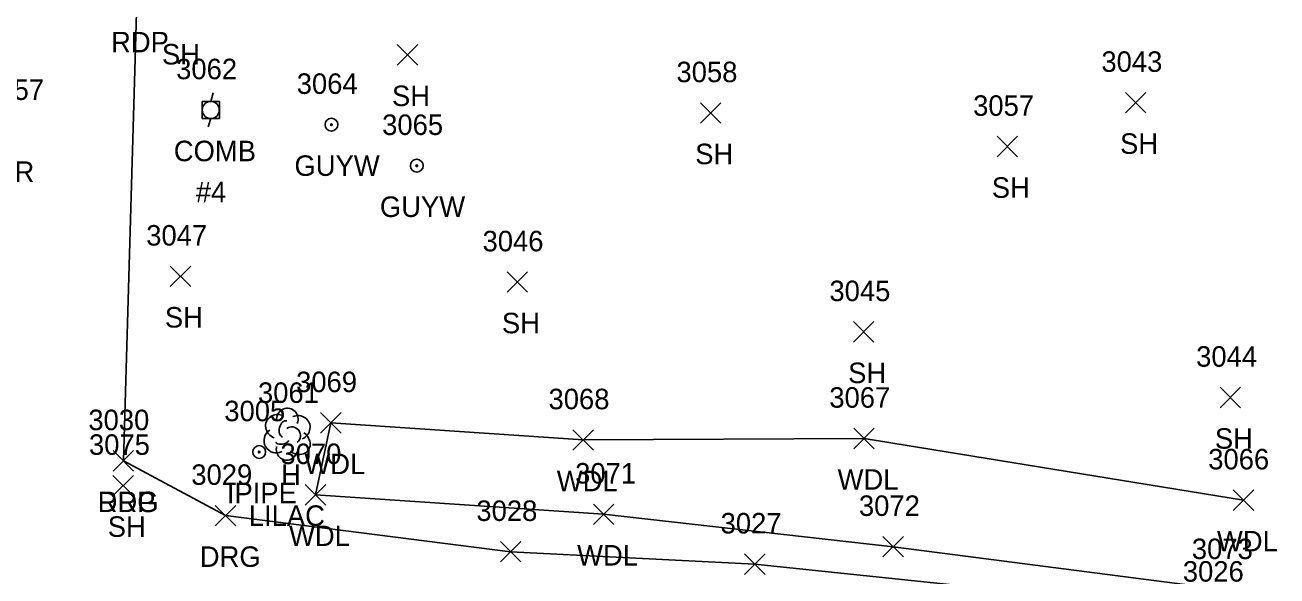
# Model space of a CAD drawing. Extents: x 1609623 to 1616187, y 756677 to 762826.
# Drawn here: x 1610613 to 1610735.2, y 762176.6 to 762230.4 of the extents above; entities that cross this region are included whole.
import ezdxf

# ---------------------------------------------------------------- set-up
doc = ezdxf.new("R2010")
doc.units = 0
for name, color, linetype in [('L_A', 7, 'Continuous'), ('L_C', 7, 'Continuous'), ('L_I', 7, 'Continuous'), ('L_TIC', 7, 'Continuous'), ('LAWA', 7, 'Continuous'), ('LTD', 7, 'Continuous'), ('M_A', 7, 'Continuous'), ('M_I', 7, 'Continuous'), ('MPIP', 7, 'Continuous'), ('P_A', 7, 'Continuous'), ('P_I', 7, 'Continuous'), ('P_TIC', 7, 'Continuous'), ('PET', 7, 'Continuous'), ('R_A', 7, 'Continuous'), ('R_I', 7, 'Continuous'), ('R_TIC', 7, 'Continuous'), ('RDG', 7, 'Continuous'), ('U_A', 7, 'Continuous'), ('U_C', 7, 'Continuous'), ('U_I', 7, 'Continuous'), ('UP', 7, 'Continuous'), ('UPGW', 7, 'Continuous')]:
    doc.layers.add(name, color=color, linetype=linetype)

msp = doc.modelspace()

# ---------------------------------------------------------------- linework, layer by layer
at = {"layer": 'L_TIC'}
for points in [[(1610649.3, 762226.48), (1610651.3, 762228.48)], [(1610651.3, 762226.48), (1610649.3, 762228.48)], [(1610720.38, 762221.82), (1610722.38, 762223.82)], [(1610722.38, 762221.82), (1610720.38, 762223.82)], [(1610678.9, 762220.81), (1610680.9, 762222.81)], [(1610680.9, 762220.81), (1610678.9, 762222.81)], [(1610707.85, 762217.53), (1610709.85, 762219.53)], [(1610709.85, 762217.53), (1610707.85, 762219.53)], [(1610627.14, 762204.87), (1610629.14, 762206.87)], [(1610629.14, 762204.87), (1610627.14, 762206.87)], [(1610660.03, 762204.31), (1610662.03, 762206.31)], [(1610662.03, 762204.31), (1610660.03, 762206.31)], [(1610693.83, 762199.45), (1610695.83, 762201.45)], [(1610695.83, 762199.45), (1610693.83, 762201.45)], [(1610729.63, 762193.05), (1610731.63, 762195.05)], [(1610731.63, 762193.05), (1610729.63, 762195.05)], [(1610641.82, 762190.57), (1610643.82, 762192.57)], [(1610643.82, 762190.57), (1610641.82, 762192.57)], [(1610666.46, 762188.9), (1610668.46, 762190.9)], [(1610668.46, 762188.9), (1610666.46, 762190.9)], [(1610693.87, 762189.05), (1610695.87, 762191.05)], [(1610695.87, 762189.05), (1610693.87, 762191.05)], [(1610621.55, 762184.45), (1610623.55, 762186.45)], [(1610623.55, 762184.45), (1610621.55, 762186.45)], [(1610640.33, 762183.55), (1610642.33, 762185.55)], [(1610642.33, 762183.55), (1610640.33, 762185.55)], [(1610730.91, 762183.03), (1610732.91, 762185.03)], [(1610732.91, 762183.03), (1610730.91, 762185.03)], [(1610668.45, 762181.65), (1610670.45, 762183.65)], [(1610670.45, 762181.65), (1610668.45, 762183.65)], [(1610696.71, 762178.49), (1610698.71, 762180.49)], [(1610698.71, 762178.49), (1610696.71, 762180.49)]]:
    msp.add_lwpolyline(points, dxfattribs=at)
at = {"layer": 'LAWA'}
msp.add_lwpolyline([(1610731.91, 762184.03), (1610694.87, 762190.05), (1610667.46, 762189.9), (1610642.82, 762191.57), (1610641.33, 762184.55), (1610669.45, 762182.65), (1610697.71, 762179.49), (1610730.21, 762175.28)], dxfattribs=at)
at = {"layer": 'LTD'}
msp.add_line((1610638.53, 762190.52), (1610638.53, 762190.52), dxfattribs=at)
msp.add_line((1610638.53, 762190.52), (1610638.53, 762190.52), dxfattribs=at)
msp.add_arc((1610638.58, 762191.95), 1.05, 335.5272, 180.9563, dxfattribs=at)
for centre, major_axis, ratio, start_param, end_param in [((1610637.74, 762191.19), (1.21, -0.51), 0.895232, 1.570796, 4.712389), ((1610638.32, 762190.98), (-0.208, -0.792), 0.645439, 3.141593, 6.283185), ((1610639.57, 762191.1), (-1.14, -0.48), 0.949671, 1.570796, 4.712389), ((1610637.45, 762189.81), (0.58, -1.04), 0.959034, 3.141593, 6.283185), ((1610639.03, 762190.35), (-0.5, 0.667), 0.989748, 3.141593, 6.283185), ((1610639.53, 762189.69), (-1.09, 0.79), 0.841452, 1.570796, 4.712389), ((1610638.53, 762189.02), (0.26, 1.06), 0.942809, 1.570796, 4.712389), ((1610638.07, 762189.77), (-0.625, -0.083), 0.423636, 0, 3.141593)]:
    msp.add_ellipse(centre, major_axis=major_axis, ratio=ratio, start_param=start_param, end_param=end_param, dxfattribs=at)
at = {"layer": 'MPIP'}
for radius in [0.625, 0.0833]:
    msp.add_circle((1610635.83, 762188.73), radius, dxfattribs=at)
at = {"layer": 'P_TIC'}
for points in [[(1610621.57, 762186.86), (1610623.57, 762188.86)], [(1610623.57, 762186.86), (1610621.57, 762188.86)]]:
    msp.add_lwpolyline(points, dxfattribs=at)
at = {"layer": 'PET'}
msp.add_lwpolyline([(1610622.57, 762187.86), (1610623.89, 762232.72), (1610625.79, 762278.17), (1610627.17, 762319.71)], dxfattribs=at)
at = {"layer": 'R_TIC'}
for points in [[(1610621.57, 762186.86), (1610623.57, 762188.86)], [(1610623.57, 762186.86), (1610621.57, 762188.86)], [(1610631.54, 762181.52), (1610633.54, 762183.52)], [(1610633.54, 762181.52), (1610631.54, 762183.52)], [(1610659.37, 762178), (1610661.37, 762180)], [(1610661.37, 762178), (1610659.37, 762180)], [(1610683.21, 762176.78), (1610685.21, 762178.78)], [(1610685.21, 762176.78), (1610683.21, 762178.78)]]:
    msp.add_lwpolyline(points, dxfattribs=at)
at = {"layer": 'RDG'}
msp.add_lwpolyline([(1610729.38, 762173.08), (1610684.21, 762177.78), (1610660.37, 762179), (1610632.54, 762182.52), (1610622.57, 762187.86)], dxfattribs=at)
at = {"layer": 'UP'}
for p, q in [((1610631.35, 762223.77), (1610631.1, 762222.94)), ((1610630.27, 762221.27), (1610630.27, 762222.94)), ((1610630.27, 762222.94), (1610631.94, 762222.94)), ((1610631.94, 762222.94), (1610631.94, 762221.27)), ((1610631.94, 762221.27), (1610630.27, 762221.27)), ((1610630.85, 762220.44), (1610631.1, 762221.27)), ((1610631.1, 762222.1), (1610631.1, 762222.1))]:
    msp.add_line(p, q, dxfattribs=at)
msp.add_circle((1610631.1, 762222.1), 0.833, dxfattribs=at)
at = {"layer": 'UPGW'}
for centre, radius in [((1610642.88, 762220.67), 0.625), ((1610642.88, 762220.67), 0.0833), ((1610651.21, 762216.66), 0.625), ((1610651.21, 762216.66), 0.0833)]:
    msp.add_circle(centre, radius, dxfattribs=at)

# ---------------------------------------------------------------- texts
at = {"layer": 'L_A'}
for s, p in [('SH', (1610626.33, 762226.54)), ('SH', (1610648.79, 762222.48)), ('SH', (1610719.86, 762217.82)), ('SH', (1610678.39, 762216.81)), ('SH', (1610707.34, 762213.53)), ('SH', (1610626.62, 762200.87)), ('SH', (1610659.52, 762200.31)), ('SH', (1610693.32, 762195.45)), ('SH', (1610729.12, 762189.05)), ('WDL', (1610640.24, 762186.57)), ('H', (1610637.97, 762185.52)), ('WDL', (1610664.88, 762184.9)), ('WDL', (1610692.29, 762185.05)), ('SH', (1610621.04, 762180.45)), ('WDL', (1610638.74, 762179.55)), ('WDL', (1610729.32, 762179.03)), ('WDL', (1610666.86, 762177.65))]:
    msp.add_text(s, height=2, dxfattribs=at).set_placement(p)
at = {"layer": 'L_C'}
msp.add_text('LILAC', height=2, dxfattribs=at).set_placement((1610634.81, 762181.52))
at = {"layer": 'L_I'}
for s, p in [('3043', (1610718.04, 762225.82)), ('3058', (1610676.56, 762224.81)), ('3057', (1610705.52, 762221.53)), ('3047', (1610624.8, 762208.87)), ('3046', (1610657.63, 762208.31)), ('3045', (1610691.49, 762203.45)), ('3044', (1610727.29, 762197.05)), ('3069', (1610639.43, 762194.57)), ('3061', (1610635.71, 762193.52)), ('3068', (1610664.07, 762192.9)), ('3067', (1610691.48, 762193.05)), ('3075', (1610619.21, 762188.45)), ('3070', (1610637.9, 762187.55)), ('3066', (1610728.47, 762187.03)), ('3071', (1610666.67, 762185.65)), ('3072', (1610694.37, 762182.49)), ('3073', (1610726.87, 762178.28))]:
    msp.add_text(s, height=2, dxfattribs=at).set_placement(p)
at = {"layer": 'M_A'}
msp.add_text('IPIPE', height=2, dxfattribs=at).set_placement((1610632.67, 762183.73))
at = {"layer": 'M_I'}
msp.add_text('3005', height=2, dxfattribs=at).set_placement((1610632.42, 762191.73))
at = {"layer": 'P_A'}
for s, p in [('RDP', (1610621.37, 762227.72)), ('CR', (1610610.01, 762215.08)), ('RDP', (1610620.06, 762182.86))]:
    msp.add_text(s, height=2, dxfattribs=at).set_placement(p)
at = {"layer": 'P_I'}
for s, p in [('3157', (1610608.88, 762223.08)), ('3030', (1610619.15, 762190.86))]:
    msp.add_text(s, height=2, dxfattribs=at).set_placement(p)
at = {"layer": 'R_A'}
for p in [(1610620.06, 762182.86), (1610630.03, 762177.52)]:
    msp.add_text('DRG', height=2, dxfattribs=at).set_placement(p)
at = {"layer": 'R_I'}
for s, p in [('3030', (1610619.15, 762190.86)), ('3029', (1610629.2, 762185.52)), ('3028', (1610657.03, 762182)), ('3027', (1610680.87, 762180.78)), ('3026', (1610725.99, 762176.08))]:
    msp.add_text(s, height=2, dxfattribs=at).set_placement(p)
at = {"layer": 'U_A'}
for s, p in [('COMB', (1610627.49, 762217.1)), ('GUYW', (1610639.27, 762215.67)), ('GUYW', (1610647.61, 762211.66))]:
    msp.add_text(s, height=2, dxfattribs=at).set_placement(p)
at = {"layer": 'U_C'}
msp.add_text('#4', height=2, dxfattribs=at).set_placement((1610629.64, 762213.1))
at = {"layer": 'U_I'}
for s, p in [('3062', (1610627.72, 762225.1)), ('3064', (1610639.49, 762223.67)), ('3065', (1610647.83, 762219.66))]:
    msp.add_text(s, height=2, dxfattribs=at).set_placement(p)

doc.saveas('drawing.dxf')
